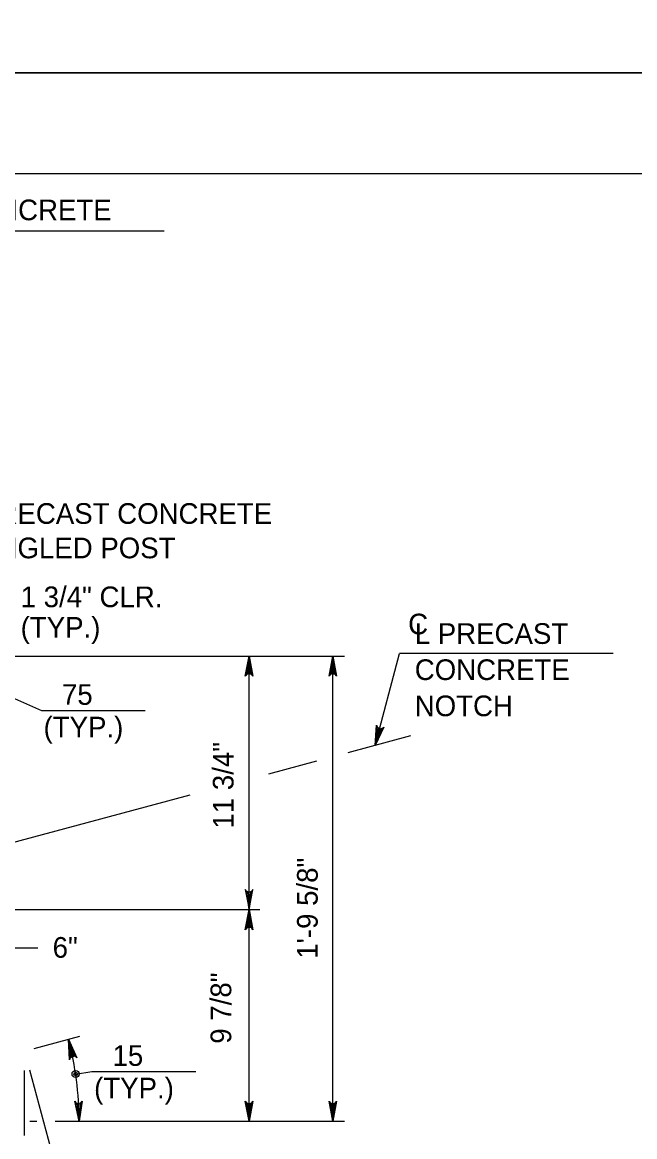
# Model space of a CAD drawing. Extents: x 3351 to 8430, y -3586 to 1457.
# Drawn here: x 5240.8 to 5331.9, y 413.5 to 579.2 of the extents above; entities that cross this region are included whole.
import ezdxf

# ---------------------------------------------------------------- set-up
doc = ezdxf.new("R2010")
doc.units = 0
for name, color, linetype in [('1', 7, 'Continuous'), ('2', 7, 'Continuous'), ('PLT-BNDY', 7, 'Continuous')]:
    doc.layers.add(name, color=color, linetype=linetype)

msp = doc.modelspace()

# ---------------------------------------------------------------- linework, layer by layer
at = {"layer": '1'}
for p, q in [((5202.2, 548.19), (5261.9, 548.19)), ((5226.39, 484.95), (5288.72, 484.95)), ((5274.53, 415.8), (5274.53, 484.95)), ((5286.99, 415.8), (5286.99, 484.95)), ((5293.27, 471.67), (5296.9, 485.34)), ((5328.68, 485.34), (5296.9, 485.34)), ((5239.19, 478.83), (5243.64, 476.85)), ((5243.64, 476.85), (5259.09, 476.85)), ((5298.57, 473.09), (5289.2, 470.58)), ((5284.55, 469.33), (5277.4, 467.42)), ((5265.74, 464.29), (5202.2, 447.27)), ((5224.42, 447.27), (5276.12, 447.27)), ((5243.11, 441.51), (5227.29, 441.51)), ((5242.57, 426.61), (5249.37, 428.44)), ((5241.14, 413.68), (5241.14, 423.32)), ((5241.89, 423.42), (5245, 411.83)), ((5248.73, 422.82), (5251.16, 423.18)), ((5251.16, 423.18), (5266.61, 423.18)), ((5241.9, 415.8), (5242.98, 415.8)), ((5245.67, 415.8), (5288.72, 415.8))]:
    msp.add_line(p, q, dxfattribs=at)
for points in [[(5274.53, 484.95), (5275.09, 481.97), (5275.01, 482.08), (5274.93, 482.2), (5274.83, 482.26), (5274.73, 482.32), (5274.63, 482.34), (5274.53, 482.35), (5274.43, 482.34), (5274.33, 482.32), (5274.23, 482.26), (5274.13, 482.2), (5274.05, 482.08), (5273.97, 481.97), (5274.53, 484.95), (5274.05, 482.08), (5274.13, 482.2), (5274.53, 484.95), (5274.23, 482.26), (5274.33, 482.32), (5274.53, 484.95), (5274.43, 482.34), (5274.53, 482.35), (5274.53, 484.95), (5274.63, 482.34), (5274.73, 482.32), (5274.53, 484.95), (5274.83, 482.26), (5274.93, 482.2), (5274.53, 484.95), (5275.01, 482.08)], [(5286.99, 484.95), (5287.55, 481.97), (5287.47, 482.08), (5287.39, 482.2), (5287.29, 482.26), (5287.19, 482.32), (5287.09, 482.34), (5286.99, 482.35), (5286.89, 482.34), (5286.79, 482.32), (5286.69, 482.26), (5286.59, 482.2), (5286.51, 482.08), (5286.43, 481.97), (5286.99, 484.95), (5286.51, 482.08), (5286.59, 482.2), (5286.99, 484.95), (5286.69, 482.26), (5286.79, 482.32), (5286.99, 484.95), (5286.89, 482.34), (5286.99, 482.35), (5286.99, 484.95), (5287.09, 482.34), (5287.19, 482.32), (5286.99, 484.95), (5287.29, 482.26), (5287.39, 482.2), (5286.99, 484.95), (5287.47, 482.08)], [(5293.27, 471.67), (5293.49, 474.69), (5293.59, 474.43), (5293.75, 474.27), (5293.94, 474.18), (5294.14, 474.16), (5294.36, 474.23), (5294.58, 474.41), (5293.27, 471.67), (5294.36, 474.23), (5294.14, 474.16), (5293.27, 471.67), (5293.94, 474.18), (5293.75, 474.27), (5293.27, 471.67), (5293.59, 474.43)], [(5274.53, 447.27), (5275.09, 450.25), (5274.93, 450.02), (5274.73, 449.9), (5274.53, 449.87), (5274.33, 449.9), (5274.13, 450.02), (5273.97, 450.25), (5274.53, 447.27), (5274.13, 450.02), (5274.33, 449.9), (5274.53, 447.27), (5274.53, 449.87), (5274.73, 449.9), (5274.53, 447.27), (5274.93, 450.02)], [(5274.53, 447.27), (5275.09, 444.28), (5274.93, 444.51), (5274.73, 444.63), (5274.53, 444.67), (5274.33, 444.63), (5274.13, 444.51), (5273.97, 444.28), (5274.53, 447.27), (5274.13, 444.51), (5274.33, 444.63), (5274.53, 447.27), (5274.53, 444.67), (5274.73, 444.63), (5274.53, 447.27), (5274.93, 444.51)], [(5247.66, 427.98), (5248.92, 425.22), (5248.71, 425.4), (5248.49, 425.47), (5248.28, 425.45), (5248.1, 425.37), (5247.93, 425.21), (5247.83, 424.95), (5247.66, 427.98), (5247.93, 425.21), (5248.1, 425.37), (5247.66, 427.98), (5248.28, 425.45), (5248.49, 425.47), (5247.66, 427.98), (5248.71, 425.4)], [(5249.24, 415.8), (5248.6, 418.77), (5248.77, 418.54), (5248.97, 418.43), (5249.17, 418.4), (5249.37, 418.44), (5249.57, 418.56), (5249.72, 418.79), (5249.24, 415.8), (5249.57, 418.56), (5249.37, 418.44), (5249.24, 415.8), (5249.17, 418.4), (5248.97, 418.43), (5249.24, 415.8), (5248.77, 418.54)], [(5274.53, 415.8), (5273.97, 418.78), (5274.05, 418.67), (5274.13, 418.55), (5274.23, 418.49), (5274.33, 418.43), (5274.43, 418.41), (5274.53, 418.4), (5274.63, 418.41), (5274.73, 418.43), (5274.83, 418.49), (5274.93, 418.55), (5275.01, 418.67), (5275.09, 418.78), (5274.53, 415.8), (5275.01, 418.67), (5274.93, 418.55), (5274.53, 415.8), (5274.83, 418.49), (5274.73, 418.43), (5274.53, 415.8), (5274.63, 418.41), (5274.53, 418.4), (5274.53, 415.8), (5274.43, 418.41), (5274.33, 418.43), (5274.53, 415.8), (5274.23, 418.49), (5274.13, 418.55), (5274.53, 415.8), (5274.05, 418.67)], [(5286.99, 415.8), (5286.43, 418.78), (5286.51, 418.67), (5286.59, 418.55), (5286.69, 418.49), (5286.79, 418.43), (5286.89, 418.41), (5286.99, 418.4), (5287.09, 418.41), (5287.19, 418.43), (5287.29, 418.49), (5287.39, 418.55), (5287.47, 418.67), (5287.55, 418.78), (5286.99, 415.8), (5287.47, 418.67), (5287.39, 418.55), (5286.99, 415.8), (5287.29, 418.49), (5287.19, 418.43), (5286.99, 415.8), (5287.09, 418.41), (5286.99, 418.4), (5286.99, 415.8), (5286.89, 418.41), (5286.79, 418.43), (5286.99, 415.8), (5286.69, 418.49), (5286.59, 418.55), (5286.99, 415.8), (5286.51, 418.67)]]:
    msp.add_lwpolyline(points, dxfattribs=at)
for radius in [0.533, 0.267]:
    msp.add_circle((5248.73, 422.82), radius, dxfattribs=at)
msp.add_arc((5203, 416.01), 46.23, 359.7348, 15, dxfattribs=at)
at = {"layer": '2'}
msp.add_line((4642.34, 556.69), (5428.34, 556.69), dxfattribs=at)
at = {"layer": 'PLT-BNDY'}
for points in [[(4602.34, 1165.69), (5443.34, 1165.69), (5443.34, 571.69), (4602.34, 571.69)], [(4602.34, 571.69), (5443.34, 571.69), (5443.34, -22.31), (4602.34, -22.31)]]:
    msp.add_lwpolyline(points, close=True, dxfattribs=at)

# ---------------------------------------------------------------- texts
at = {"layer": '1'}
for s, height, p in [('L PRECAST CONCRETE', 3.0721, (5207.07, 549.76)), ('PRECAST CONCRETE', 3.0721, (5234.37, 504.62)), ('ANGLED POST', 3.0721, (5234.37, 499.5)), ('1 3/4" CLR.', 3.0721, (5240.55, 492.23)), ('(TYP.)', 3.072, (5240.55, 487.69)), ('C', 3.07, (5298.2, 488.19)), ('L PRECAST', 3.072, (5299.18, 486.77)), ('CONCRETE', 3.072, (5299.18, 481.4)), ('75', 3.072, (5246.7, 477.71)), ('NOTCH', 3.072, (5299.18, 476.02)), ('(TYP.)', 3.072, (5243.96, 472.86)), ('6"', 3.072, (5245.31, 440.11)), ('15', 3.072, (5254.22, 424.03)), ('(TYP.)', 3.072, (5251.48, 419.19))]:
    msp.add_text(s, height=height, dxfattribs=at).set_placement(p)
for s, p in [('11 3/4"', (5272.22, 459.31)), ('1\'-9 5/8"', (5284.74, 439.95)), ('9 7/8"', (5271.88, 427.32))]:
    msp.add_text(s, height=3.072, rotation=90, dxfattribs=at).set_placement(p)

doc.saveas('drawing.dxf')
